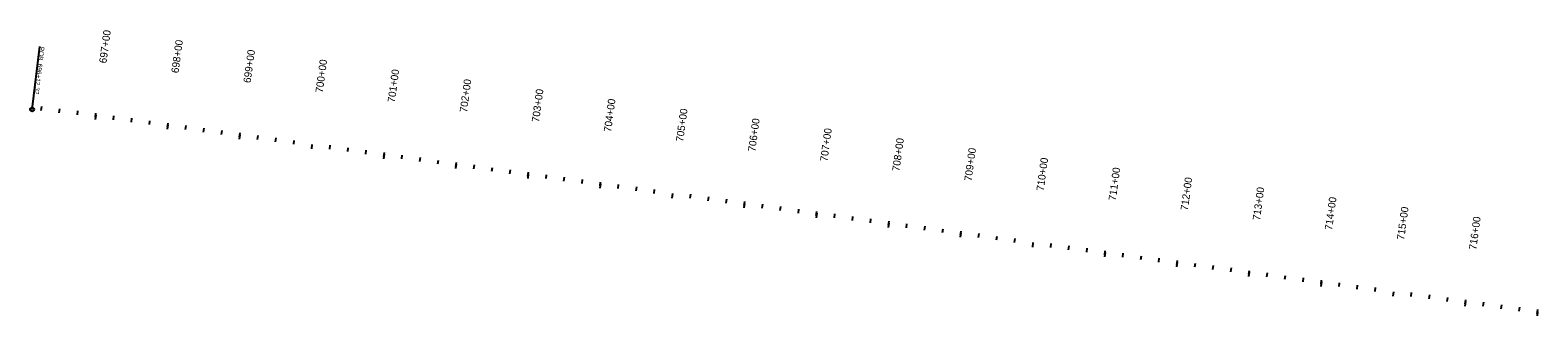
# Model space of a CAD drawing. Extents: x 19404354 to 19412652, y 7588762 to 7591481.
# Drawn here: x 19404354 to 19406426, y 7591089 to 7591481 of the extents above; entities that cross this region are included whole.
import ezdxf

# ---------------------------------------------------------------- set-up
doc = ezdxf.new("R2010")
doc.units = 0
for name, color, linetype in [('dsnNonPlotable', 7, 'Continuous'), ('dsnStdShading', 7, 'Continuous'), ('EdgeShoulder', 7, 'Continuous')]:
    doc.layers.add(name, color=color, linetype=linetype)

msp = doc.modelspace()

# ---------------------------------------------------------------- linework, layer by layer
at = {"layer": 'dsnNonPlotable'}
msp.add_line((19404356.8, 7591372.7), (19404367.3, 7591459.1), dxfattribs=at)
msp.add_circle((19404356.8, 7591372.7), 2.67, dxfattribs=at)
at = {"layer": 'dsnStdShading'}
for p, q in [((19404443.8, 7591361.9), (19404444.5, 7591367.3)), ((19404542.9, 7591348.4), (19404543.6, 7591353.8)), ((19404641.9, 7591334.9), (19404642.7, 7591340.3)), ((19404741.4, 7591324.5), (19404740.6, 7591318.4)), ((19404840.1, 7591307.9), (19404840.9, 7591313.4)), ((19404939.2, 7591294.5), (19404939.9, 7591299.9)), ((19405038.3, 7591281), (19405039, 7591286.4)), ((19405137.4, 7591267.5), (19405138.1, 7591272.9)), ((19405236.9, 7591257.1), (19405236.1, 7591251)), ((19405335.6, 7591240.5), (19405336.3, 7591246)), ((19405434.6, 7591227.1), (19405435.4, 7591232.5)), ((19405533.7, 7591213.6), (19405534.5, 7591219)), ((19405632.8, 7591200.1), (19405633.6, 7591205.5)), ((19405732.3, 7591189.7), (19405731.5, 7591183.6)), ((19405831, 7591173.1), (19405831.7, 7591178.5)), ((19405930.1, 7591159.7), (19405930.8, 7591165.1)), ((19406029.2, 7591146.2), (19406029.9, 7591151.6)), ((19406128.3, 7591132.7), (19406129, 7591138.1)), ((19406227.8, 7591122.2), (19406226.9, 7591116.2)), ((19406326.4, 7591105.7), (19406327.2, 7591111.1)), ((19406425.5, 7591092.3), (19406426.2, 7591097.7))]:
    msp.add_line(p, q, dxfattribs=at)
at = {"layer": 'EdgeShoulder'}
for p, q in [((19404369.4, 7591371.2), (19404370, 7591376.6)), ((19404394.2, 7591368.2), (19404394.8, 7591373.6)), ((19404419, 7591365.1), (19404419.6, 7591370.5)), ((19404444.2, 7591364.9), (19404443.4, 7591358.8)), ((19404468.5, 7591358.5), (19404469.3, 7591363.9)), ((19404493.3, 7591355.1), (19404494, 7591360.5)), ((19404518.1, 7591351.8), (19404518.8, 7591357.2)), ((19404543.3, 7591351.4), (19404542.4, 7591345.4)), ((19404567.6, 7591345), (19404568.4, 7591350.4)), ((19404592.4, 7591341.6), (19404593.1, 7591347.1)), ((19404617.2, 7591338.3), (19404617.9, 7591343.7)), ((19404642.4, 7591337.9), (19404641.5, 7591331.9)), ((19404666.7, 7591331.5), (19404667.5, 7591336.9)), ((19404691.5, 7591328.2), (19404692.2, 7591333.6)), ((19404716.3, 7591324.8), (19404717, 7591330.2)), ((19404741.4, 7591324.5), (19404740.6, 7591318.4)), ((19404765.8, 7591318.1), (19404766.5, 7591323.5)), ((19404790.6, 7591314.7), (19404791.3, 7591320.1)), ((19404815.3, 7591311.3), (19404816.1, 7591316.7)), ((19404840.5, 7591311), (19404839.7, 7591304.9)), ((19404864.9, 7591304.6), (19404865.6, 7591310)), ((19404889.7, 7591301.2), (19404890.4, 7591306.6)), ((19404914.4, 7591297.8), (19404915.2, 7591303.2)), ((19404939.6, 7591297.5), (19404938.8, 7591291.4)), ((19404964, 7591291.1), (19404964.7, 7591296.5)), ((19404988.7, 7591287.7), (19404989.5, 7591293.1)), ((19405013.5, 7591284.4), (19405014.3, 7591289.8)), ((19405038.7, 7591284), (19405037.9, 7591278)), ((19405063.1, 7591277.6), (19405063.8, 7591283)), ((19405087.8, 7591274.2), (19405088.6, 7591279.7)), ((19405112.6, 7591270.9), (19405113.3, 7591276.3)), ((19405137.8, 7591270.5), (19405137, 7591264.5)), ((19405162.2, 7591264.1), (19405162.9, 7591269.5)), ((19405186.9, 7591260.8), (19405187.7, 7591266.2)), ((19405211.7, 7591257.4), (19405212.4, 7591262.8)), ((19405236.9, 7591257.1), (19405236.1, 7591251)), ((19405261.2, 7591250.7), (19405262, 7591256.1)), ((19405286, 7591247.3), (19405286.7, 7591252.7)), ((19405310.8, 7591243.9), (19405311.5, 7591249.3)), ((19405336, 7591243.6), (19405335.1, 7591237.5)), ((19405360.3, 7591237.2), (19405361.1, 7591242.6)), ((19405385.1, 7591233.8), (19405385.8, 7591239.2)), ((19405409.9, 7591230.4), (19405410.6, 7591235.8)), ((19405435.1, 7591230.1), (19405434.2, 7591224)), ((19405459.4, 7591223.7), (19405460.1, 7591229.1)), ((19405484.2, 7591220.3), (19405484.9, 7591225.7)), ((19405509, 7591217), (19405509.7, 7591222.4)), ((19405534.1, 7591216.6), (19405533.3, 7591210.5)), ((19405558.5, 7591210.2), (19405559.2, 7591215.6)), ((19405583.3, 7591206.8), (19405584, 7591212.3)), ((19405608, 7591203.5), (19405608.8, 7591208.9)), ((19405633.2, 7591203.1), (19405632.4, 7591197.1)), ((19405657.6, 7591196.7), (19405658.3, 7591202.1)), ((19405682.4, 7591193.4), (19405683.1, 7591198.8)), ((19405707.1, 7591190), (19405707.9, 7591195.4)), ((19405732.3, 7591189.7), (19405731.5, 7591183.6)), ((19405756.7, 7591183.2), (19405757.4, 7591188.7)), ((19405781.4, 7591179.9), (19405782.2, 7591185.3)), ((19405806.2, 7591176.5), (19405807, 7591181.9)), ((19405831.4, 7591176.2), (19405830.6, 7591170.1)), ((19405855.8, 7591169.8), (19405856.5, 7591175.2)), ((19405880.5, 7591166.4), (19405881.3, 7591171.8)), ((19405905.3, 7591163), (19405906, 7591168.4)), ((19405930.5, 7591162.7), (19405929.7, 7591156.6)), ((19405954.8, 7591156.3), (19405955.6, 7591161.7)), ((19405979.6, 7591152.9), (19405980.4, 7591158.3)), ((19406004.4, 7591149.5), (19406005.1, 7591155)), ((19406029.6, 7591149.2), (19406028.8, 7591143.1)), ((19406053.9, 7591142.8), (19406054.7, 7591148.2)), ((19406078.7, 7591139.4), (19406079.4, 7591144.8)), ((19406103.5, 7591136.1), (19406104.2, 7591141.5)), ((19406128.7, 7591135.7), (19406127.8, 7591129.7)), ((19406153, 7591129.3), (19406153.8, 7591134.7)), ((19406177.8, 7591126), (19406178.5, 7591131.4)), ((19406202.6, 7591122.6), (19406203.3, 7591128)), ((19406227.8, 7591122.2), (19406226.9, 7591116.2)), ((19406252.1, 7591115.8), (19406252.8, 7591121.3)), ((19406276.9, 7591112.5), (19406277.6, 7591117.9)), ((19406301.7, 7591109.1), (19406302.4, 7591114.5)), ((19406326.8, 7591108.8), (19406326, 7591102.7)), ((19406351.2, 7591102.4), (19406351.9, 7591107.8)), ((19406376, 7591099), (19406376.7, 7591104.4)), ((19406400.7, 7591095.6), (19406401.5, 7591101)), ((19406425.9, 7591095.3), (19406425.1, 7591089.2))]:
    msp.add_line(p, q, dxfattribs=at)

# ---------------------------------------------------------------- texts
at = {"layer": 'dsnNonPlotable'}
for s, p in [('POB ', (19404367.4, 7591459.1)), ('696+12.32', (19404364.6, 7591435.9))]:
    msp.add_text(s, height=6.48, rotation=263.0235, dxfattribs=at).set_placement(p)
at = {"layer": 'dsnStdShading'}
for s, p in [('700+00', (19404756.2, 7591395.1)), ('705+00', (19405251.6, 7591327.7)), ('710+00', (19405747.1, 7591260.2)), ('715+00', (19406242.5, 7591192.8))]:
    msp.add_text(s, height=10.2, rotation=82.2525, dxfattribs=at).set_placement(p)
at = {"layer": 'EdgeShoulder'}
for s, p in [('697+00', (19404458.9, 7591435.5)), ('698+00', (19404558, 7591422)), ('699+00', (19404657.1, 7591408.5)), ('700+00', (19404756.2, 7591395.1)), ('701+00', (19404855.3, 7591381.6)), ('702+00', (19404954.4, 7591368.1)), ('703+00', (19405053.5, 7591354.6)), ('704+00', (19405152.5, 7591341.1)), ('705+00', (19405251.6, 7591327.7)), ('706+00', (19405350.7, 7591314.2)), ('707+00', (19405449.8, 7591300.7)), ('708+00', (19405548.9, 7591287.2)), ('709+00', (19405648, 7591273.7)), ('710+00', (19405747.1, 7591260.2)), ('711+00', (19405846.2, 7591246.8)), ('712+00', (19405945.2, 7591233.3)), ('713+00', (19406044.3, 7591219.8)), ('714+00', (19406143.4, 7591206.3)), ('715+00', (19406242.5, 7591192.8)), ('716+00', (19406341.6, 7591179.4))]:
    msp.add_text(s, height=10.2, rotation=82.2525, dxfattribs=at).set_placement(p)

doc.saveas('drawing.dxf')
